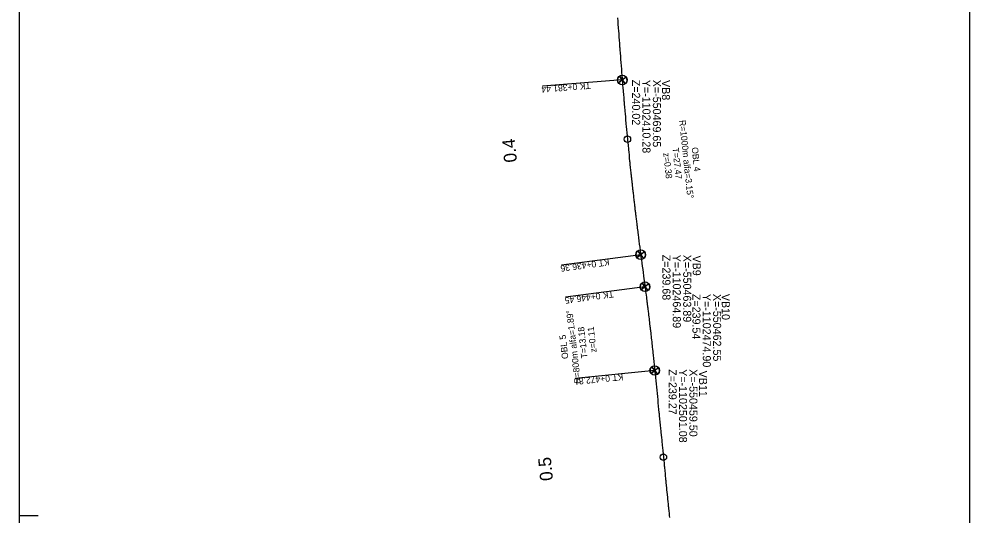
# Model space of a CAD drawing. Extents: x -583517 to -548566, y -1166112 to -1101582.
# Drawn here: x -550658.1 to -550361.1, y -1102546.5 to -1102391.2 of the extents above; entities that cross this region are included whole.
import ezdxf

# ---------------------------------------------------------------- set-up
doc = ezdxf.new("R2010")
doc.units = 0
for name, color, linetype in [('13', 7, 'Continuous'), ('59', 7, 'Continuous'), ('8', 7, 'Continuous'), ('Body pricny rez', 7, 'Continuous'), ('Popis PP', 7, 'Continuous'), ('Rámy', 7, 'Continuous')]:
    doc.layers.add(name, color=color, linetype=linetype)

msp = doc.modelspace()

# ---------------------------------------------------------------- linework, layer by layer
at = {"layer": '13'}
for points in [[(-550469.65, -1102410.28), (-550494.57, -1102412.22)], [(-550463.89, -1102464.89), (-550488.67, -1102468.2)], [(-550462.55, -1102474.9), (-550487.33, -1102478.2)], [(-550459.5, -1102501.08), (-550484.38, -1102503.57)]]:
    msp.add_lwpolyline(points, dxfattribs=at)
at = {"layer": '8'}
for p, q in [((-550468.44, -1102409.39), (-550470.85, -1102411.18)), ((-550470.85, -1102411.18), (-550469.65, -1102410.28)), ((-550470.85, -1102411.18), (-550469.65, -1102410.28)), ((-550470.54, -1102409.08), (-550468.75, -1102411.49)), ((-550469.65, -1102410.28), (-550470.54, -1102409.08)), ((-550469.65, -1102410.28), (-550470.54, -1102409.08)), ((-550468.44, -1102409.39), (-550469.65, -1102410.28)), ((-550469.65, -1102410.28), (-550468.75, -1102411.49)), ((-550462.68, -1102464), (-550465.09, -1102465.79)), ((-550464.78, -1102463.69), (-550462.99, -1102466.1)), ((-550463.89, -1102464.89), (-550464.78, -1102463.69)), ((-550463.89, -1102464.89), (-550464.78, -1102463.69)), ((-550462.68, -1102464), (-550463.89, -1102464.89)), ((-550465.09, -1102465.79), (-550463.89, -1102464.89)), ((-550465.09, -1102465.79), (-550463.89, -1102464.89)), ((-550463.89, -1102464.89), (-550462.99, -1102466.1)), ((-550461.35, -1102474), (-550463.76, -1102475.79)), ((-550463.76, -1102475.79), (-550462.55, -1102474.9)), ((-550463.76, -1102475.79), (-550462.55, -1102474.9)), ((-550462.55, -1102474.9), (-550463.45, -1102473.69)), ((-550462.55, -1102474.9), (-550463.45, -1102473.69)), ((-550463.45, -1102473.7), (-550461.66, -1102476.1)), ((-550461.35, -1102474), (-550462.55, -1102474.9)), ((-550462.55, -1102474.9), (-550461.66, -1102476.1)), ((-550458.3, -1102500.19), (-550460.71, -1102501.98)), ((-550460.71, -1102501.98), (-550459.5, -1102501.08)), ((-550460.71, -1102501.98), (-550459.5, -1102501.08)), ((-550460.4, -1102499.88), (-550458.61, -1102502.29)), ((-550459.5, -1102501.08), (-550460.4, -1102499.88)), ((-550459.5, -1102501.08), (-550460.4, -1102499.88)), ((-550458.3, -1102500.19), (-550459.5, -1102501.08)), ((-550459.5, -1102501.08), (-550458.61, -1102502.29))]:
    msp.add_line(p, q, dxfattribs=at)
for centre in [(-550469.65, -1102410.28), (-550463.89, -1102464.89), (-550462.55, -1102474.9), (-550459.5, -1102501.08)]:
    msp.add_circle(centre, 1.5, dxfattribs=at)
for centre, start, end in [((-550469.65, -1102410.28), 126.6271, 216.6271), ((-550469.65, -1102410.28), 126.6271, 216.6271), ((-550469.65, -1102410.28), 306.6271, 36.6271), ((-550463.89, -1102464.89), 126.6271, 216.6271), ((-550463.89, -1102464.89), 126.6271, 216.6271), ((-550463.89, -1102464.89), 306.6271, 36.6271), ((-550462.55, -1102474.9), 126.6271, 216.6271), ((-550462.55, -1102474.9), 126.6271, 216.6271), ((-550462.55, -1102474.9), 306.6271, 36.6271), ((-550459.5, -1102501.08), 126.6271, 216.6271), ((-550459.5, -1102501.08), 126.6271, 216.6271), ((-550459.5, -1102501.08), 306.6271, 36.6271)]:
    msp.add_arc(centre, 1.5, start, end, dxfattribs=at)
at = {"layer": 'Body pricny rez'}
msp.add_lwpolyline([(-550471.16, -1102390.9), (-550471.08, -1102391.9), (-550471.03, -1102392.58), (-550471.02, -1102392.59), (-550471.01, -1102392.73), (-550471, -1102392.86), (-550471, -1102392.9), (-550470.92, -1102393.9), (-550470.91, -1102394.12), (-550470.85, -1102394.89), (-550470.77, -1102395.89), (-550470.69, -1102396.89), (-550470.61, -1102397.88), (-550470.54, -1102398.88), (-550470.46, -1102399.88), (-550470.43, -1102400.25), (-550470.38, -1102400.87), (-550470.3, -1102401.87), (-550470.22, -1102402.87), (-550470.15, -1102403.87), (-550470.07, -1102404.86), (-550469.99, -1102405.86), (-550469.91, -1102406.86), (-550469.84, -1102407.85), (-550469.76, -1102408.85), (-550469.68, -1102409.85), (-550469.68, -1102409.92), (-550469.65, -1102410.28), (-550469.6, -1102410.84), (-550469.53, -1102411.84), (-550469.45, -1102412.84), (-550469.39, -1102413.59), (-550469.38, -1102413.71), (-550469.37, -1102413.84), (-550469.28, -1102414.83), (-550469.2, -1102415.83), (-550469.12, -1102416.82), (-550469.09, -1102417.12), (-550469.06, -1102417.54), (-550469.03, -1102417.82), (-550468.95, -1102418.82), (-550468.86, -1102419.81), (-550468.84, -1102420.02), (-550468.77, -1102420.81), (-550468.68, -1102421.81), (-550468.6, -1102422.8), (-550468.5, -1102423.8), (-550468.49, -1102423.96), (-550468.41, -1102424.79), (-550468.32, -1102425.79), (-550468.23, -1102426.79), (-550468.13, -1102427.78), (-550468.04, -1102428.78), (-550468, -1102429.17), (-550467.94, -1102429.77), (-550467.84, -1102430.77), (-550467.84, -1102430.8), (-550467.74, -1102431.76), (-550467.7, -1102432.2), (-550467.64, -1102432.76), (-550467.54, -1102433.75), (-550467.44, -1102434.75), (-550467.35, -1102435.64), (-550467.34, -1102435.71), (-550467.34, -1102435.73), (-550467.34, -1102435.74), (-550467.33, -1102435.84), (-550467.26, -1102436.53), (-550467.24, -1102436.74), (-550467.14, -1102437.63), (-550467.13, -1102437.73), (-550467.06, -1102438.41), (-550467.03, -1102438.66), (-550467.03, -1102438.72), (-550466.99, -1102439.06), (-550466.95, -1102439.46), (-550466.94, -1102439.54), (-550466.92, -1102439.72), (-550466.9, -1102439.87), (-550466.86, -1102440.27), (-550466.82, -1102440.67), (-550466.81, -1102440.71), (-550466.77, -1102441.07), (-550466.73, -1102441.47), (-550466.7, -1102441.71), (-550466.69, -1102441.88), (-550466.67, -1102442.04), (-550466.64, -1102442.28), (-550466.6, -1102442.68), (-550466.59, -1102442.7), (-550466.55, -1102443.08), (-550466.51, -1102443.48), (-550466.48, -1102443.7), (-550466.46, -1102443.88), (-550466.42, -1102444.29), (-550466.4, -1102444.45), (-550466.37, -1102444.69), (-550466.37, -1102444.69), (-550466.37, -1102444.71), (-550466.33, -1102445.09), (-550466.28, -1102445.49), (-550466.26, -1102445.68), (-550466.24, -1102445.89), (-550466.19, -1102446.3), (-550466.15, -1102446.68), (-550466.14, -1102446.7), (-550466.1, -1102447.1), (-550466.05, -1102447.5), (-550466.03, -1102447.67), (-550466.01, -1102447.9), (-550465.96, -1102448.3), (-550465.92, -1102448.66), (-550465.91, -1102448.71), (-550465.87, -1102449.11), (-550465.82, -1102449.51), (-550465.8, -1102449.66), (-550465.77, -1102449.91), (-550465.72, -1102450.31), (-550465.68, -1102450.65), (-550465.68, -1102450.71), (-550465.63, -1102451.11), (-550465.61, -1102451.27), (-550465.58, -1102451.52), (-550465.56, -1102451.64), (-550465.53, -1102451.92), (-550465.48, -1102452.32), (-550465.45, -1102452.64), (-550465.44, -1102452.72), (-550465.39, -1102453.12), (-550465.38, -1102453.17), (-550465.34, -1102453.52), (-550465.33, -1102453.55), (-550465.33, -1102453.63), (-550465.29, -1102453.92), (-550465.24, -1102454.33), (-550465.2, -1102454.62), (-550465.19, -1102454.73), (-550465.14, -1102455.13), (-550465.11, -1102455.41), (-550465.09, -1102455.53), (-550465.08, -1102455.61), (-550465.04, -1102455.93), (-550464.96, -1102456.61), (-550464.83, -1102457.6), (-550464.83, -1102457.63), (-550464.83, -1102457.64), (-550464.81, -1102457.8), (-550464.77, -1102458.07), (-550464.77, -1102458.09), (-550464.71, -1102458.59), (-550464.58, -1102459.58), (-550464.45, -1102460.57), (-550464.33, -1102461.57), (-550464.2, -1102462.56), (-550464.07, -1102463.55), (-550463.94, -1102464.54), (-550463.89, -1102464.89), (-550463.8, -1102465.53), (-550463.67, -1102466.52), (-550463.54, -1102467.51), (-550463.41, -1102468.5), (-550463.27, -1102469.5), (-550463.14, -1102470.49), (-550463.01, -1102471.48), (-550462.88, -1102472.47), (-550462.75, -1102473.46), (-550462.61, -1102474.45), (-550462.55, -1102474.9), (-550462.55, -1102474.9), (-550462.48, -1102475.44), (-550462.43, -1102475.87), (-550462.35, -1102476.43), (-550462.35, -1102476.43), (-550462.28, -1102476.99), (-550462.22, -1102477.43), (-550462.2, -1102477.55), (-550462.13, -1102478.11), (-550462.09, -1102478.42), (-550462.06, -1102478.68), (-550461.99, -1102479.24), (-550461.97, -1102479.41), (-550461.93, -1102479.71), (-550461.92, -1102479.8), (-550461.87, -1102480.16), (-550461.86, -1102480.26), (-550461.85, -1102480.36), (-550461.84, -1102480.4), (-550461.84, -1102480.42), (-550461.77, -1102480.92), (-550461.72, -1102481.39), (-550461.71, -1102481.43), (-550461.7, -1102481.48), (-550461.63, -1102482.05), (-550461.59, -1102482.39), (-550461.56, -1102482.61), (-550461.54, -1102482.77), (-550461.5, -1102483.17), (-550461.47, -1102483.38), (-550461.45, -1102483.54), (-550461.43, -1102483.73), (-550461.36, -1102484.29), (-550461.35, -1102484.37), (-550461.29, -1102484.85), (-550461.23, -1102485.36), (-550461.22, -1102485.42), (-550461.16, -1102485.98), (-550461.11, -1102486.36), (-550461.09, -1102486.54), (-550461.02, -1102487.1), (-550460.99, -1102487.35), (-550460.96, -1102487.67), (-550460.92, -1102487.98), (-550460.89, -1102488.23), (-550460.88, -1102488.34), (-550460.83, -1102488.79), (-550460.76, -1102489.34), (-550460.76, -1102489.35), (-550460.7, -1102489.91), (-550460.65, -1102490.33), (-550460.63, -1102490.48), (-550460.57, -1102491.04), (-550460.54, -1102491.32), (-550460.51, -1102491.6), (-550460.46, -1102491.98), (-550460.44, -1102492.16), (-550460.43, -1102492.32), (-550460.38, -1102492.73), (-550460.32, -1102493.29), (-550460.32, -1102493.31), (-550460.26, -1102493.85), (-550460.21, -1102494.31), (-550460.2, -1102494.41), (-550460.18, -1102494.53), (-550460.13, -1102494.98), (-550460.1, -1102495.3), (-550460.07, -1102495.54), (-550459.99, -1102496.29), (-550459.89, -1102497.29), (-550459.79, -1102498.28), (-550459.68, -1102499.28), (-550459.58, -1102500.27), (-550459.53, -1102500.76), (-550459.5, -1102501.08), (-550459.48, -1102501.27), (-550459.48, -1102501.3), (-550459.47, -1102501.35), (-550459.44, -1102501.67), (-550459.38, -1102502.26), (-550459.28, -1102503.26), (-550459.18, -1102504.25), (-550459.08, -1102505.25), (-550458.99, -1102506.24), (-550458.89, -1102507.24), (-550458.79, -1102508.23), (-550458.69, -1102509.23), (-550458.59, -1102510.22), (-550458.49, -1102511.22), (-550458.39, -1102512.21), (-550458.29, -1102513.21), (-550458.19, -1102514.2), (-550458.16, -1102514.48), (-550458.09, -1102515.2), (-550457.99, -1102516.19), (-550457.89, -1102517.19), (-550457.79, -1102518.18), (-550457.69, -1102519.18), (-550457.6, -1102520.08), (-550457.59, -1102520.17), (-550457.57, -1102520.43), (-550457.49, -1102521.17), (-550457.39, -1102522.16), (-550457.34, -1102522.73), (-550457.3, -1102523.1), (-550457.3, -1102523.15), (-550457.3, -1102523.16), (-550457.27, -1102523.4), (-550457.2, -1102524.15), (-550457.16, -1102524.52), (-550457.1, -1102525.15), (-550457, -1102526.14), (-550456.9, -1102527.14), (-550456.8, -1102528.13), (-550456.7, -1102529.13), (-550456.6, -1102530.12), (-550456.51, -1102531.01), (-550456.5, -1102531.12), (-550456.44, -1102531.74), (-550456.4, -1102532.11), (-550456.36, -1102532.48), (-550456.3, -1102533.11), (-550456.29, -1102533.21), (-550456.22, -1102533.95), (-550456.2, -1102534.1), (-550456.14, -1102534.68), (-550456.1, -1102535.1), (-550456.07, -1102535.41), (-550456, -1102536.1), (-550456, -1102536.15), (-550455.92, -1102536.88), (-550455.9, -1102537.09), (-550455.85, -1102537.62), (-550455.8, -1102538.09), (-550455.78, -1102538.35), (-550455.7, -1102539.08), (-550455.7, -1102539.09), (-550455.63, -1102539.82), (-550455.6, -1102540.08), (-550455.56, -1102540.56), (-550455.51, -1102541.07), (-550455.48, -1102541.29), (-550455.41, -1102542.03), (-550455.41, -1102542.07), (-550455.34, -1102542.76), (-550455.31, -1102543.06), (-550455.26, -1102543.49), (-550455.23, -1102543.82), (-550455.21, -1102544.06), (-550455.2, -1102544.17), (-550455.19, -1102544.23), (-550455.12, -1102544.96), (-550455.11, -1102545.05), (-550455.04, -1102545.7), (-550455.01, -1102545.98), (-550455.01, -1102546.05), (-550454.97, -1102546.43), (-550454.91, -1102547.04)], dxfattribs=at)
for centre in [(-550468.04, -1102428.78), (-550456.8, -1102528.13)]:
    msp.add_circle(centre, 1, dxfattribs=at)
at = {"layer": 'Popis PP'}
msp.add_line((-550658.05, -1102546.4), (-550652.05, -1102546.4), dxfattribs=at)
at = {"layer": 'Rámy'}
msp.add_lwpolyline([(-550658.05, -1102021.4), (-550658.05, -1102756.4), (-550361.05, -1102756.4), (-550361.05, -1102021.4)], close=True, dxfattribs=at)

# ---------------------------------------------------------------- texts
at = {"layer": '13'}
for s, height, rotation, p in [('TK 0+381.44', 2, 184.4476, (-550479.62, -1102411.06)), ('R=1000m alfa=3.15%%d', 2, 276.021, (-550451.89, -1102422.92)), ('0.4', 4, 95.5113, (-550502.52, -1102435.87)), ('   z=0.38', 2, 276.021, (-550457.08, -1102430.91)), ('  T=27.47', 2, 276.021, (-550454.15, -1102430.06)), ('OBL 4', 2, 276.021, (-550447.98, -1102431.4)), ('KT 0+436.36', 2, 187.5944, (-550473.8, -1102466.22)), ('TK 0+446.45', 2, 187.5944, (-550472.47, -1102476.22)), ('R=800m alfa=1.89%%d', 2, 96.6504, (-550482.54, -1102505.01)), ('  T=13.18', 2, 96.6504, (-550480.27, -1102498.62)), ('   z=0.11', 2, 96.6504, (-550477.37, -1102497.54)), ('OBL 5', 2, 96.6504, (-550486.46, -1102497.35)), ('KT 0+472.81', 2, 185.7064, (-550469.45, -1102502.08)), ('0.5', 4, 95.7064, (-550491.25, -1102535.37))]:
    msp.add_text(s, height=height, rotation=rotation, dxfattribs=at).set_placement(p)
at = {"layer": '59'}
for s, p in [('Z=240.02', (-550466.56, -1102410.22)), ('Y=-1102410.28', (-550463.33, -1102410.22)), ('X=-550469.65', (-550460.09, -1102410.22)), ('VB8', (-550457.24, -1102410.3)), ('Z=239.68', (-550457.09, -1102464.89)), ('Y=-1102464.89', (-550453.86, -1102464.89)), ('X=-550463.89', (-550450.62, -1102464.89)), ('VB9', (-550447.63, -1102465.13)), ('Z=239.54', (-550447.73, -1102477.12)), ('Y=-1102474.90', (-550444.49, -1102477.12)), ('X=-550462.55', (-550441.26, -1102477.12)), ('VB10', (-550438.56, -1102477.11)), ('Z=239.27', (-550455.16, -1102500.66)), ('Y=-1102501.08', (-550451.92, -1102500.66)), ('X=-550459.50', (-550448.69, -1102500.66)), ('VB11', (-550445.64, -1102501.11))]:
    msp.add_text(s, height=2.5, rotation=270, dxfattribs=at).set_placement(p)

doc.saveas('drawing.dxf')
